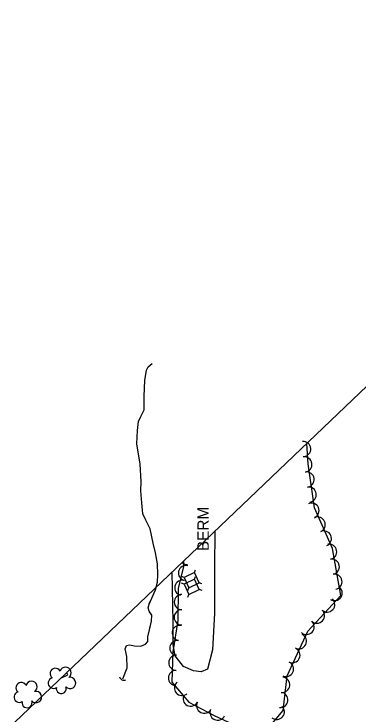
# Model space of a CAD drawing. Extents: x 588843 to 2552415, y 180129 to 269402.
# Drawn here: x 592346.6 to 592526.9, y 187683.2 to 188050.1 of the extents above; entities that cross this region are included whole.
import ezdxf

# ---------------------------------------------------------------- set-up
doc = ezdxf.new("R2010")
doc.units = 0
for name, color, linetype in [('Default', 7, 'Continuous'), ('Level 12', 7, 'Continuous'), ('Level 15', 7, 'Continuous'), ('Level 17', 7, 'Continuous'), ('Level 18', 7, 'Continuous'), ('Level 19', 7, 'Continuous'), ('Level 21', 7, 'Continuous')]:
    doc.layers.add(name, color=color, linetype=linetype)

msp = doc.modelspace()

# ---------------------------------------------------------------- linework, layer by layer
at = {"layer": 'Default'}
msp.add_lwpolyline([(592409.33, 187552.38), (592387.7, 187602.85), (592346.9, 187678.64), (592735.79, 188050.05), (592838.09, 187808.48), (592884.47, 187677.08), (592985.3, 187391.41)], close=True, dxfattribs=at)
at = {"layer": 'Level 12'}
msp.add_lwpolyline([(592371.45, 187702.09), (592374.81, 187703.68), (592374.31, 187704.82)], dxfattribs=at)
at = {"layer": 'Level 15'}
msp.add_arc((592404.1, 187703.14), 2.25, 191.1605, 297.4, dxfattribs=at)
at = {"layer": 'Level 17'}
msp.add_lwpolyline([(592451.89, 187778.91), (592451.65, 187760.38), (592451.64, 187735.94), (592450.68, 187716.84), (592448.02, 187706.64), (592444.65, 187705.24), (592440.67, 187705.78), (592435.39, 187708.12), (592431.11, 187713.63), (592429.91, 187719.4), (592430.01, 187731.3), (592429.51, 187757.54)], dxfattribs=at)
at = {"layer": 'Level 18'}
msp.add_lwpolyline([(592435.42, 187763.18), (592435.41, 187760.41), (592432.52, 187748.89), (592432.4, 187732.13), (592429.74, 187715.7), (592429.35, 187699.82), (592438.15, 187689.44), (592451.53, 187682.43), (592466.55, 187675.46), (592477.56, 187672.94), (592487.62, 187685.01), (592489.73, 187703.19), (592500.66, 187726.62), (592517.88, 187745.27), (592513.54, 187769.98), (592504.12, 187791.18), (592500.83, 187814.28), (592500.02, 187824.88)], dxfattribs=at)
for centre, radius, start, end in [((592498.14, 187822.07), 4, 274.3609, 94.3456), ((592498.76, 187813.96), 4, 278.1155, 98.1002), ((592499.89, 187806.05), 4, 278.1155, 98.1002), ((592501.02, 187798.14), 4, 278.1155, 98.1002), ((592502.48, 187789.73), 4, 293.9674, 113.9521), ((592505.72, 187782.43), 4, 293.9674, 113.9521), ((592508.97, 187775.13), 4, 293.9674, 113.9521), ((592511.73, 187768.22), 4, 279.9557, 99.9404), ((592437.52, 187765.45), 4, 226.3737, 269.8436), ((592513.11, 187760.35), 4, 279.9557, 99.9404), ((592436.72, 187757.04), 4, 75.9375, 255.9222), ((592514.49, 187752.48), 4, 279.9557, 99.9404), ((592434.78, 187749.29), 4, 75.9375, 255.9222), ((592514.6, 187746.6), 4, 237.3038, 57.2884), ((592434.56, 187741.82), 4, 89.5734, 269.5581), ((592510.72, 187740.59), 4, 227.3038, 47.2884), ((592434.5, 187733.84), 4, 89.5734, 269.5581), ((592505.3, 187734.72), 4, 227.3038, 47.2884), ((592433.46, 187725.61), 4, 80.8407, 260.8254), ((592499.88, 187728.85), 4, 227.3038, 47.2884), ((592432.19, 187717.72), 4, 80.8407, 260.8254), ((592495.86, 187721.27), 4, 244.9833, 64.9679), ((592492.48, 187714.03), 4, 244.9833, 64.9679), ((592431.69, 187710.05), 4, 88.5719, 268.5565), ((592368.23, 187704.35), 2.78, 26.4761, 234.2491), ((592373.59, 187704.8), 2.97, 303.5052, 164.7391), ((592489.1, 187706.79), 4, 244.9833, 64.9679), ((592431.49, 187702.06), 4, 88.5719, 268.5565), ((592350.32, 187696.95), 2.78, 26.4761, 234.2491), ((592355.68, 187697.41), 2.97, 303.5052, 164.7391), ((592367.24, 187699.38), 2.78, 103.1531, 304.1641), ((592375.97, 187699.45), 2.97, 221.156, 104.1293), ((592434.62, 187696.83), 4, 130.2898, 310.2744), ((592487.08, 187698.47), 4, 263.3924, 83.377), ((592371.34, 187696.44), 2.61, 165.8612, 23.7938), ((592349.34, 187691.99), 2.78, 103.1531, 304.1641), ((592358.06, 187692.06), 2.97, 221.156, 104.1293), ((592439.18, 187691.25), 4, 152.3823, 332.367), ((592486.16, 187690.53), 4, 263.3924, 83.377), ((592353.43, 187689.05), 2.61, 165.8612, 23.7938), ((592446.26, 187687.55), 4, 152.3823, 332.367), ((592453.27, 187683.93), 4, 155.1235, 335.1082), ((592484.3, 187684.3), 4, 230.1965, 50.1812)]:
    msp.add_arc(centre, radius, start, end, dxfattribs=at)
at = {"layer": 'Level 19'}
for points in [[(592403.68, 187701.54), (592405.88, 187707.38), (592405.62, 187713.36), (592404.77, 187717.31), (592405.61, 187719.09), (592407.12, 187719.37), (592409.65, 187718.93), (592413.11, 187718.75), (592415.49, 187719.75), (592416.65, 187721.1), (592416.72, 187723.68), (592417.52, 187727.35), (592418.61, 187731.91), (592418.8, 187734.94), (592417.49, 187737.05), (592416.95, 187738.8), (592417.34, 187740.76), (592418.72, 187743.88), (592420.76, 187748.21), (592421.74, 187752.33), (592421.97, 187756.24), (592421.84, 187761.9), (592420.77, 187767.67), (592419.58, 187772.68), (592417.9, 187780.14), (592415.6, 187784.75), (592414.07, 187788.11), (592413.56, 187793.83), (592413.04, 187800.18), (592413.25, 187805.1), (592412.73, 187814.09), (592410.91, 187824.76), (592411.26, 187831.82), (592411.85, 187836.55), (592413.11, 187839.04), (592414.73, 187842.54), (592414.82, 187849.78), (592415.2, 187857.98), (592416.03, 187863.35), (592416.57, 187864.5), (592416.87, 187865.07), (592419.04, 187866.82)], [(592417.49, 187741.1), (592418.4, 187743.17)], [(592418.79, 187734.83), (592418.8, 187734.94), (592417.66, 187736.77)], [(592417.71, 187728.16), (592418.24, 187730.36)], [(592403.68, 187701.54), (592405.88, 187707.38), (592405.62, 187713.36), (592404.77, 187717.31), (592405.61, 187719.09), (592407.12, 187719.37), (592409.65, 187718.93), (592413.11, 187718.75), (592415.49, 187719.75), (592416.65, 187721.1), (592416.72, 187723.68), (592416.73, 187723.74)]]:
    msp.add_lwpolyline(points, dxfattribs=at)
at = {"layer": 'Level 21'}
for p, q in [((592441.14, 187757.28), (592441.65, 187758.69)), ((592435.71, 187754.74), (592434.3, 187755.25)), ((592441.15, 187753.81), (592441.66, 187755.22)), ((592435.72, 187751.27), (592434.31, 187751.78)), ((592445.09, 187751.33), (592443.68, 187751.85)), ((592437.74, 187747.89), (592438.25, 187749.3)), ((592445.1, 187747.87), (592443.69, 187748.38)), ((592437.75, 187744.42), (592438.26, 187745.83))]:
    msp.add_line(p, q, dxfattribs=at)
for points in [[(592438.25, 187749.3), (592443.68, 187751.85), (592441.14, 187757.28), (592435.71, 187754.74)], [(592438.26, 187745.83), (592443.69, 187748.38), (592441.15, 187753.81), (592435.72, 187751.27)]]:
    msp.add_lwpolyline(points, close=True, dxfattribs=at)

# ---------------------------------------------------------------- texts
at = {"layer": 'Level 17'}
msp.add_text('BERM', height=6, rotation=90.0815, dxfattribs=at).set_placement((592448.68, 187768.57))

doc.saveas('drawing.dxf')
